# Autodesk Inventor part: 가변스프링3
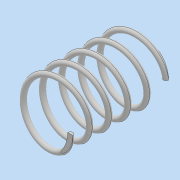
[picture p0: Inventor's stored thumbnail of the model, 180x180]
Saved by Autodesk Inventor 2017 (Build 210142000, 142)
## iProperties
Part Number: 가변스프링3
Material: 일반
Document SubType Name: Modeling
Designer: MRC
Density: 1 g/cm^3
Appearance: 기본값
Author: MRC
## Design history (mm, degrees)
sketch "스케치1"
  geometry: L1 (0, 0)-(11, 0); L2 (11, 0)-(11, 37.411); L3 (11, 37.411)-(0, 37.411); L4 (0, 37.411)-(0, 0); C1 r 1 at (11, 0)
  constraints: 8 end point, 2 parallel, 1 centre point, 1 coincident, 1 horizontal, 1 perpendicular
  dimensions: "d0" = 22 diameter of L2 L4; "d1" = 2 diameter of C1; "d2" = 37.4112 distance between parallel lines of L1 L3 (derived)
feature "코일1" sketch "스케치1" pitch "d3" = 10; turns "d5" = 5; dims "d4" = 37.4112 (= d2), "d6" = 0, angle "d7" = 90 deg, angle "d8" = 90 deg, "d9" = 0, "d10" = 0
sketch "스케치2"
  geometry: L1 (-25.076, 37.411)-(25.076, 37.411); L2 (25.076, 37.411)-(25.076, 0); L3 (25.076, 0)-(-25.076, 0); L4 (-25.076, 0)-(-25.076, 37.411); L5 (0, 37.411)-(0, 0) reference; 2 further points
  constraints: 8 end point, 2 midpoint, 2 parallel, 1 coincident, 1 horizontal, 1 perpendicular
  dimensions: "d11" = 50.15108 distance of L1.start L1.end
extrude "돌출1" sketch "스케치2" stored distance "d12" = 0; taper "d13" = 0 deg
node "솔리드1"
